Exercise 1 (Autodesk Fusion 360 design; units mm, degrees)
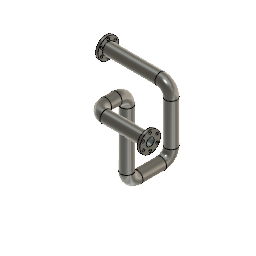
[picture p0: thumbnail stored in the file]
sketch "Sketch1" plane through (0, 0, 0) normal (0, 0, 1) x axis (1, 0, 0)
  dimension "d1" = 240
  dimension "d2" = 240
  dimension "d3" = 170
  dimension "d4" = 300
  dimension "d5" = 120
  dimension "d6" = 200
  dimension "d7" = 40
pipe "Pipe1" SectionSize 45 SectionThickness 7.5
sketch "Sketch2" plane through (440, 0, 0) normal (1, 0, 0) x axis (0, 1, 0)
  circle C1 centre (-290, 60) radius 15
  circle C2 centre (-290, 60) radius 22.5
sketch "Sketch3" plane through (440, 0, 0) normal (1, 0, 0) x axis (0, 1, 0)
  circle C1 centre (-290, 60) radius 40
  circle C2 centre (-290, 60) radius 15
  circle C3 centre (-290, 60) radius 15
  point P2 (-290, 60)
  point P3 (-290, 60)
  point P4 (-290, 60)
  coincident P2 P3
  coincident P3 P4
  equal C2 C3
  dimension "d12" diameter C1 = 80
extrude "Extrude1" add sketch "Sketch3" along normal blind 10
sketch "Sketch4" plane through (0, 0, 0) normal (-1, 0, 0) x axis (0, -1, 0)
  circle C1 centre (0, 0) radius 15
  circle C2 centre (0, 0) radius 22.5
  circle C3 centre (0, 0) radius 40
  circle C4 centre (0, 0) radius 15
  point P1 (0, 0)
  point P3 (0, 0)
  point P4 (0, 0)
  coincident P1 P3
  coincident P1 P4
  equal C1 C4
  dimension "d15" diameter C3 = 80
extrude "Extrude2" add sketch "Sketch4" along normal blind 10
sketch "Sketch6" plane through (450, 0, 0) normal (1, 0, 0) x axis (0, 1, 0)
  circle C1 centre (-290, 60) radius 15
  circle C2 centre (-290, 60) radius 40
  circle C3 centre (-290, 60) radius 30
  circle C4 centre (-290, 90) radius 5
  point P4 (-290, 90)
  point P3 (-290, 60)
  concentric C1 C3
  coincident C3 P4
  vertical P3 P4
  dimension "d19" diameter C3 = 60
  dimension "d20" diameter C4 = 10
extrude "Extrude3" cut sketch "Sketch6" profile of C4 to an object
circular_pattern "C-Pattern1" TotalAngle 360
sketch "Sketch7" plane through (-10, 0, 0) normal (-1, 0, 0) x axis (0, -1, 0)
  circle C1 centre (0, 0) radius 15
  circle C2 centre (0, 0) radius 40
  circle C3 centre (0, 0) radius 30
  circle C4 centre (0, 30) radius 5
  point P1 (0, 0)
  point P3 (0, 0)
  point P4 (0, 30)
  coincident P1 P3
  coincident C3 P4
  vertical P3 P4
  dimension "d25" diameter C3 = 60
  dimension "d26" diameter C4 = 10
extrude "Extrude4" cut sketch "Sketch7" profile of C4 to an object
circular_pattern "C-Pattern2" TotalAngle 360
